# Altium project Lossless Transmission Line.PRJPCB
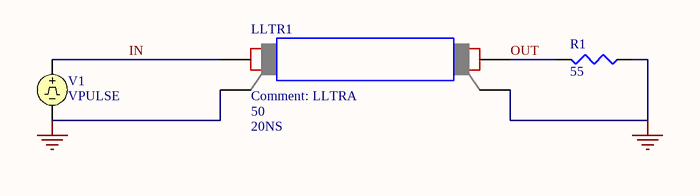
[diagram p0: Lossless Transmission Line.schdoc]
1 sheet, 3 parts. Net scope: global (net labels, ports and power ports of the same name join across sheets).

## Sheet Lossless Transmission Line.schdoc: Lossless Transmission Line
size A4; Organization: Altium Limited; Address1: L3, 12a Rodborough Rd; Address2: Frenchs Forest; Address3: NSW; Address4: Australia 2086; DocumentNumber: 1; SheetNumber: 1; SheetTotal: 1

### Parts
LLTR1  LLTRA  Char. Impedance: 50  Transmission Delay: 20NS
R1  55
V1  VPULSE

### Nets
GND: LLTR1.2(N1-) LLTR1.4(N2-) R1.2(BOT) V1.2
IN: LLTR1.1(N1+) V1.1
OUT: LLTR1.3(N2+) R1.1(TOP)

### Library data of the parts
LLTR1 = LLTRA: Lossless Transmission Line
R1 = RES: Resistor
V1 = VPULSE: Pulse Voltage Source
